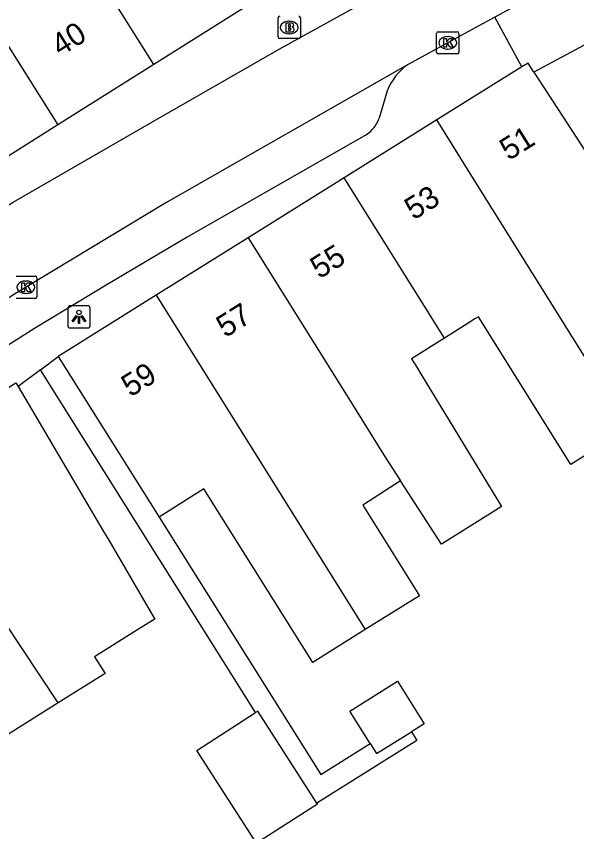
# Model space of a CAD drawing. Extents: x 161801 to 162379, y 382315 to 382832.
# Drawn here: x 161979.42 to 162004.55, y 382498.82 to 382535.41 of the extents above; entities that cross this region are included whole.
import ezdxf

# ---------------------------------------------------------------- set-up
doc = ezdxf.new("R2010")
doc.units = 0
for name, color, linetype in [('IMGEO_Brandkraan', 7, 'Continuous'), ('IMGEO_Kolk', 7, 'Continuous'), ('IMGEO_Lichtpunt', 7, 'Continuous'), ('IMGEO_Pand', 7, 'Continuous'), ('IMGEO_Pand_nummerreeks', 7, 'Continuous'), ('IMGEO_Rijbaan_lokaal_open', 7, 'Continuous'), ('IMGEO_Voetpad_open', 7, 'Continuous')]:
    doc.layers.add(name, color=color, linetype=linetype)

msp = doc.modelspace()

# ---------------------------------------------------------------- linework, layer by layer
at = {"layer": 'IMGEO_Brandkraan'}
for p, q in [((161991.156, 382534.479), (161991.156, 382535.331)), ((161992.157, 382535.331), (161992.157, 382534.479)), ((161991.644, 382535.185), (161991.669, 382535.185)), ((161991.667, 382534.625), (161991.642, 382534.625)), ((161992.083, 382534.405), (161991.231, 382534.405))]:
    msp.add_line(p, q, dxfattribs=at)
for points in [[(161991.156, 382534.479), (161991.156, 382535.331)], [(161992.157, 382535.331), (161992.157, 382534.479)], [(161991.504, 382535.105), (161991.504, 382534.705), (161991.717, 382534.705)], [(161991.735, 382535.105), (161991.504, 382535.105)], [(161991.683, 382535.024), (161991.629, 382535.024), (161991.629, 382534.948)], [(161991.629, 382534.948), (161991.682, 382534.948)], [(161991.691, 382534.872), (161991.629, 382534.872), (161991.629, 382534.791)], [(161991.629, 382534.791), (161991.691, 382534.791)], [(161992.083, 382534.405), (161991.231, 382534.405)]]:
    msp.add_lwpolyline(points, dxfattribs=at)
for centre, radius, start, end in [((161991.233, 382535.329), 0.0765, 91.552, 178.448), ((161991.233, 382535.329), 0.0765, 91.552, 178.448), ((161992.081, 382535.329), 0.0765, 1.552, 88.448), ((161992.081, 382535.329), 0.0765, 1.552, 88.448), ((161991.684, 382534.986), 0.0379, 267.8285, 90.9355), ((161991.739, 382534.96), 0.145, 59.4692, 91.5367), ((161991.764, 382535.007), 0.0922, 285.5137, 58.1501), ((161991.769, 382534.815), 0.105, 301.3115, 78.989), ((161991.692, 382534.831), 0.0404, 269.8759, 90.5077), ((161991.723, 382534.956), 0.251, 268.6676, 293.5347), ((161991.233, 382534.481), 0.0765, 181.552, 268.448), ((161991.233, 382534.481), 0.0765, 181.552, 268.448), ((161992.081, 382534.481), 0.0765, 271.552, 358.448), ((161992.081, 382534.481), 0.0765, 271.552, 358.448)]:
    msp.add_arc(centre, radius, start, end, dxfattribs=at)
for centre, major_axis, ratio, start_param, end_param in [((161991.643, 382534.905), (-0.387, 0.002), 0.722429, 4.712389, 7.853982), ((161991.668, 382534.905), (-0.39, 0.002), 0.717154, 1.570796, 4.712389)]:
    msp.add_ellipse(centre, major_axis=major_axis, ratio=ratio, start_param=start_param, end_param=end_param, dxfattribs=at)
at = {"layer": 'IMGEO_Kolk'}
for p, q in [((161998.265, 382533.789), (161998.265, 382534.641)), ((161998.34, 382534.715), (161999.192, 382534.715)), ((161999.266, 382534.641), (161999.266, 382533.789)), ((161998.753, 382534.495), (161998.778, 382534.495)), ((161998.776, 382533.935), (161998.751, 382533.935)), ((161999.192, 382533.715), (161998.34, 382533.715)), ((161979.416, 382523.747), (161980.268, 382523.747)), ((161980.342, 382523.673), (161980.342, 382522.821)), ((161979.829, 382523.527), (161979.854, 382523.527)), ((161979.852, 382522.967), (161979.827, 382522.967)), ((161980.268, 382522.747), (161979.416, 382522.747))]:
    msp.add_line(p, q, dxfattribs=at)
for points in [[(161998.265, 382533.789), (161998.265, 382534.641)], [(161998.34, 382534.715), (161999.192, 382534.715)], [(161999.266, 382534.641), (161999.266, 382533.789)], [(161998.586, 382534.415), (161998.709, 382534.415), (161998.709, 382534.264), (161998.839, 382534.415), (161999.003, 382534.415), (161998.857, 382534.264), (161999.01, 382534.015), (161998.858, 382534.015), (161998.773, 382534.179), (161998.709, 382534.112), (161998.709, 382534.015), (161998.586, 382534.015), (161998.586, 382534.415)], [(161999.192, 382533.715), (161998.34, 382533.715)], [(161979.416, 382523.747), (161980.268, 382523.747)], [(161980.342, 382523.673), (161980.342, 382522.821)], [(161979.662, 382523.447), (161979.785, 382523.447), (161979.785, 382523.296), (161979.915, 382523.447), (161980.079, 382523.447), (161979.933, 382523.296), (161980.086, 382523.047), (161979.934, 382523.047), (161979.849, 382523.211), (161979.785, 382523.144), (161979.785, 382523.047), (161979.662, 382523.047), (161979.662, 382523.447)], [(161980.268, 382522.747), (161979.416, 382522.747)]]:
    msp.add_lwpolyline(points, dxfattribs=at)
for centre, start, end in [((161998.342, 382534.639), 91.552, 178.448), ((161998.342, 382534.639), 91.552, 178.448), ((161999.19, 382534.639), 1.552, 88.448), ((161999.19, 382534.639), 1.552, 88.448), ((161998.342, 382533.791), 181.552, 268.448), ((161998.342, 382533.791), 181.552, 268.448), ((161999.19, 382533.791), 271.552, 358.448), ((161999.19, 382533.791), 271.552, 358.448), ((161980.266, 382523.671), 1.552, 88.448), ((161980.266, 382523.671), 1.552, 88.448), ((161980.266, 382522.823), 271.552, 358.448), ((161980.266, 382522.823), 271.552, 358.448)]:
    msp.add_arc(centre, 0.0765, start, end, dxfattribs=at)
for centre, major_axis, ratio, start_param, end_param in [((161998.752, 382534.215), (-0.387, 0.002), 0.722429, 4.712389, 7.853982), ((161998.777, 382534.215), (-0.39, 0.002), 0.717154, 1.570796, 4.712389), ((161979.828, 382523.247), (-0.387, 0.002), 0.722429, 4.712389, 7.853982), ((161979.853, 382523.247), (-0.39, 0.002), 0.717154, 1.570796, 4.712389)]:
    msp.add_ellipse(centre, major_axis=major_axis, ratio=ratio, start_param=start_param, end_param=end_param, dxfattribs=at)
at = {"layer": 'IMGEO_Lichtpunt'}
for p, q in [((161981.73, 382522.322), (161981.73, 382521.515)), ((161981.73, 382522.322), (161981.73, 382521.515)), ((161982.632, 382522.417), (161981.824, 382522.417)), ((161982.632, 382522.417), (161981.824, 382522.417)), ((161982.726, 382521.515), (161982.726, 382522.322)), ((161982.726, 382521.515), (161982.726, 382522.322)), ((161981.824, 382521.421), (161982.632, 382521.421)), ((161981.824, 382521.421), (161982.632, 382521.421))]:
    msp.add_line(p, q, dxfattribs=at)
for points in [[(161982.104, 382521.986), (161982.143, 382521.958), (161981.955, 382521.696), (161981.917, 382521.723), (161982.104, 382521.986)], [(161982.206, 382521.938), (161982.253, 382521.938), (161982.253, 382521.616), (161982.206, 382521.616), (161982.206, 382521.938)], [(161982.316, 382521.958), (161982.354, 382521.985), (161982.541, 382521.723), (161982.502, 382521.695), (161982.316, 382521.958)]]:
    msp.add_lwpolyline(points, dxfattribs=at)
msp.add_circle((161982.229, 382522.12), 0.0994, dxfattribs=at)
for centre, start, end in [((161981.824, 382522.322), 90, 180), ((161981.824, 382522.322), 90, 180), ((161982.632, 382522.322), 0, 90), ((161982.632, 382522.322), 0, 90), ((161981.824, 382521.515), 180, 270), ((161981.824, 382521.515), 180, 270), ((161982.632, 382521.515), 270, 0), ((161982.632, 382521.515), 270, 360)]:
    msp.add_arc(centre, 0.0946, start, end, dxfattribs=at)
at = {"layer": 'IMGEO_Pand'}
for points in [[(161972.324, 382544.765), (161981.283, 382530.533)], [(161985.588, 382533.244), (161981.145, 382540.302)], [(161991.824, 382537.171), (161985.588, 382533.244)], [(161985.588, 382533.244), (161981.283, 382530.533)], [(162002.092, 382533.131), (161998.271, 382530.756)], [(162002.633, 382532.892), (162002.367, 382533.301), (162002.092, 382533.131)], [(162002.633, 382532.892), (162007.095, 382526.032), (162005.526, 382525.045), (162009.567, 382518.617), (162006.904, 382516.943)], [(161981.283, 382530.533), (161977.027, 382527.853)], [(161998.271, 382530.756), (161994.122, 382528.161)], [(162006.904, 382516.943), (162000, 382527.989), (161998.271, 382530.756)], [(161994.122, 382528.161), (161989.813, 382525.467)], [(161998.618, 382520.967), (161994.122, 382528.161)], [(161989.813, 382525.467), (161985.691, 382522.889)], [(161989.813, 382525.467), (161994.313, 382518.265), (161995.96, 382515.629), (161996.647, 382514.565)], [(161985.691, 382522.889), (161981.298, 382520.142)], [(161985.691, 382522.889), (161995.066, 382507.886)], [(162006.904, 382516.943), (162004.293, 382515.302), (162000.143, 382521.924), (161999.985, 382521.825), (161999.68, 382521.633), (161998.618, 382520.967)], [(161998.618, 382520.967), (161997.144, 382520.042), (161997.376, 382519.66), (161997.572, 382519.339), (162001.183, 382513.409), (162000.921, 382513.244), (162000.686, 382513.097), (161998.485, 382511.718), (161996.647, 382514.565)], [(161981.298, 382520.142), (161983.956, 382515.908), (161985.821, 382512.937)], [(161974, 382515.595), (161979.401, 382518.966), (161979.504, 382518.791)], [(161979.504, 382518.791), (161983.319, 382512.288), (161983.558, 382511.894), (161985.33, 382508.866), (161985.628, 382508.359), (161985.332, 382508.173), (161984.777, 382507.825), (161982.918, 382506.659), (161983.395, 382505.912), (161981.3, 382504.598)], [(161981.3, 382504.598), (161974, 382515.595)], [(161996.647, 382514.565), (161994.964, 382513.478), (161997.494, 382509.41), (161995.066, 382507.886)], [(161995.066, 382507.886), (161992.923, 382506.541), (161992.717, 382506.412), (161987.829, 382514.197), (161985.821, 382512.937)], [(161981.3, 382504.598), (161978.244, 382502.682), (161975.499, 382507.059), (161973.405, 382505.746), (161969.132, 382512.557)], [(161995.284, 382502.781), (161994.376, 382504.227), (161996.514, 382505.569), (161997.707, 382503.66), (161997.143, 382503.306)], [(161992.897, 382500.102), (161990.243, 382504.229), (161990.146, 382504.167)], [(161992.897, 382500.102), (161992.924, 382500.06), (161990.186, 382498.299), (161987.505, 382502.468), (161990.146, 382504.167)], [(161995.284, 382502.781), (161995.573, 382502.321), (161997.143, 382503.306)]]:
    msp.add_lwpolyline(points, dxfattribs=at)
at = {"layer": 'IMGEO_Rijbaan_lokaal_open'}
for points in [[(162007.323, 382538.877), (162000.874, 382535.365)], [(161948.095, 382507.457), (161949.145, 382508.117), (161953.15, 382510.607), (161979.276, 382527.063), (161985.491, 382530.651), (161991.203, 382533.931), (161998.314, 382537.876)], [(162000.874, 382535.365), (162000, 382534.889), (161996.967, 382533.235)], [(161996.967, 382533.235), (161986.125, 382527.031), (161979.411, 382522.988), (161956.057, 382508.297)]]:
    msp.add_lwpolyline(points, dxfattribs=at)
at = {"layer": 'IMGEO_Voetpad_open'}
for points in [[(162002.092, 382533.131), (162000.874, 382535.365)], [(162005.114, 382534.226), (162002.633, 382532.892)], [(161996.046, 382532.06), (161995.683, 382530.835)], [(161995.101, 382530.091), (161987.08, 382525.499), (161983.445, 382523.349), (161980.229, 382521.393), (161973.467, 382517.114), (161959.365, 382508.249)], [(161980.496, 382519.538), (161981.298, 382520.142)], [(161980.496, 382519.538), (161979.504, 382518.791)], [(161990.146, 382504.167), (161980.496, 382519.538)], [(161985.821, 382512.937), (161993.069, 382501.391), (161995.284, 382502.781)], [(161997.143, 382503.306), (161997.385, 382502.919), (161992.897, 382500.102)]]:
    msp.add_lwpolyline(points, dxfattribs=at)
for centre, radius, start, end in [((161998.495, 382531.089), 2.634, 125.4481, 158.3711), ((161994.397, 382531.241), 1.348, 301.4603, 342.4705)]:
    msp.add_arc(centre, radius, start, end, dxfattribs=at)

# ---------------------------------------------------------------- texts
at = {"layer": 'IMGEO_Pand_nummerreeks'}
for s, rotation, p in [('40', 32.1959, (161981.392, 382533.58)), ('51', 32.0169, (162001.5, 382528.906)), ('53', 32.0169, (161997.235, 382526.24)), ('55', 32.0169, (161993.006, 382523.595)), ('57', 32.0169, (161988.79, 382520.959)), ('59', 32.0169, (161984.533, 382518.297))]:
    msp.add_text(s, height=1, rotation=rotation, dxfattribs=at).set_placement(p)

doc.saveas('drawing.dxf')
